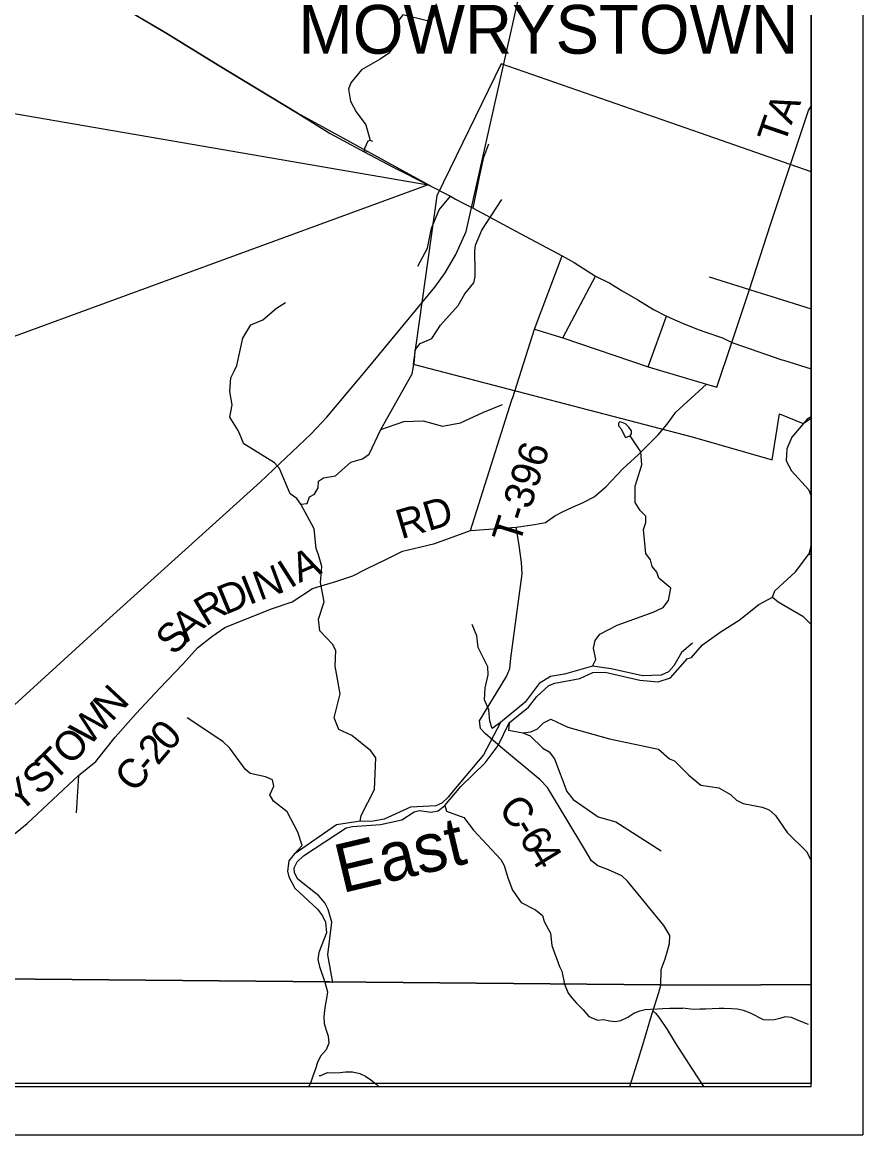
# Model space of a CAD drawing. Extents: x 0 to 34, y 0 to 22.
# Drawn here: x 7.367 to 9, y 14 to 16.162 of the extents above; entities that cross this region are included whole.
import ezdxf

# ---------------------------------------------------------------- set-up
doc = ezdxf.new("R2010")
doc.units = 0
for name, color, linetype in [('Default', 7, 'Continuous'), ('GM_X_City_Street', 7, 'Continuous'), ('GM_X_Corporation_Text', 7, 'Continuous'), ('GM_X_County_Road', 7, 'Continuous'), ('GM_X_County_Road_Text', 7, 'Continuous'), ('GM_X_Major_River', 7, 'Continuous'), ('GM_X_Major_River_Text', 7, 'Continuous'), ('GM_X_Minor_Lake', 7, 'Continuous'), ('GM_X_Minor_River', 7, 'Continuous'), ('GM_X_Rail_Line', 7, 'Continuous'), ('GM_X_State_Route', 7, 'Continuous'), ('GM_X_Township_Road', 7, 'Continuous'), ('GM_X_Township_Road_Text', 7, 'Continuous'), ('SH_Cut_Line', 7, 'Continuous'), ('SH_Data', 7, 'Continuous')]:
    doc.layers.add(name, color=color, linetype=linetype)

msp = doc.modelspace()

# ---------------------------------------------------------------- linework, layer by layer
at = {"layer": 'Default'}
msp.add_lwpolyline([(8.161, 15.8436), (7.9019, 15.9854), (7.7478, 16.0791), (7.6481, 16.1403), (7.4293, 16.2693), (7.2434, 16.3742), (6.998, 16.5438), (6.6485, 16.765), (6.4043, 16.9203), (6.0579, 17.1312), (5.7891, 17.2948), (5.4666, 17.4969), (4.8712, 17.8663), (4.7185, 17.9622), (4.6135, 18.0087), (4.4868, 18.0434), (4.3784, 18.0545), (4.2056, 18.0659), (3.9354, 18.0836), (3.6991, 18.1432)], dxfattribs=at)
for points in [[(8.9, 15.3927), (8.9, 15.8717), (8.685, 15.9464), (8.2976, 16.0814), (8.1729, 15.8246), (8.1267, 15.4975), (8.6688, 15.3564), (8.8242, 15.3119), (8.8384, 15.4014), (8.8841, 15.3823)], [(7.2008, 16.011), (8.1557, 15.8464), (7.2008, 15.4965)], [(7.3096, 14.0941), (8.9, 14.0941), (8.9, 14.2922), (8.7041, 14.2905), (8.6074, 14.2911), (7.3204, 14.3032)]]:
    msp.add_lwpolyline(points, close=True, dxfattribs=at)
at = {"layer": 'GM_X_City_Street'}
for p, q in [((8.4172, 15.5492), (8.4806, 15.6688)), ((8.8046, 15.6353), (8.8217, 15.6299)), ((8.8217, 15.6299), (8.9, 15.6054)), ((8.5832, 15.4923), (8.6188, 15.5911))]:
    msp.add_line(p, q, dxfattribs=at)
for points in [[(8.2431, 15.8007), (8.2553, 15.8615), (8.2638, 15.9002), (8.2737, 15.9259)], [(8.1359, 15.6885), (8.1546, 15.723), (8.162, 15.762), (8.1773, 15.7976), (8.199, 15.8241)], [(8.7014, 15.6676), (8.7797, 15.6431), (8.8046, 15.6353)], [(8.3624, 15.566), (8.4172, 15.5492), (8.5832, 15.4923), (8.6963, 15.4587)]]:
    msp.add_lwpolyline(points, dxfattribs=at)
at = {"layer": 'GM_X_County_Road'}
for points in [[(8.8581, 15.8821), (8.8587, 15.884), (8.8945, 15.9907), (8.9, 15.9994)], [(8.7459, 15.54), (8.7797, 15.6431), (8.8211, 15.7693), (8.8581, 15.8821)], [(8.6202, 15.381), (8.637, 15.4042), (8.6963, 15.4587), (8.7166, 15.4527), (8.7459, 15.54)], [(7.1628, 14.4308), (7.3766, 14.605), (7.4762, 14.6982), (7.51, 14.7255), (7.5477, 14.7727), (7.5884, 14.819), (7.6336, 14.8672), (7.6793, 14.9145), (7.7079, 14.9463), (7.7353, 14.9682), (7.761, 14.9856), (7.8172, 15.0084), (7.8512, 15.0222), (7.8917, 15.0356), (7.9309, 15.0614), (7.9542, 15.069), (7.9763, 15.075), (8.0092, 15.0866), (8.036, 15.1001), (8.0746, 15.1184), (8.1057, 15.1345), (8.1392, 15.1419), (8.1689, 15.1493), (8.2378, 15.1743), (8.3267, 15.181), (8.3621, 15.186), (8.3838, 15.1902), (8.4018, 15.2028), (8.4168, 15.2105), (8.4363, 15.22), (8.4566, 15.2287), (8.4781, 15.2401), (8.5012, 15.2594), (8.5337, 15.2941), (8.5642, 15.3224), (8.6028, 15.3601), (8.6202, 15.381)], [(8.6076, 14.2905), (8.6085, 14.3213), (8.6161, 14.3421), (8.6209, 14.3572), (8.6249, 14.3715), (8.6252, 14.3875), (8.6138, 14.407), (8.5432, 14.493), (8.532, 14.5034), (8.5063, 14.5149), (8.4852, 14.5229), (8.4729, 14.5322), (8.46, 14.5545), (8.3873, 14.6746), (8.3735, 14.6897), (8.2964, 14.7541), (8.2665, 14.7801), (8.2572, 14.7897), (8.2555, 14.8042), (8.3079, 14.8905), (8.3146, 14.906), (8.3161, 14.9261), (8.3384, 15.0904), (8.3372, 15.1121), (8.3325, 15.1452), (8.3267, 15.181)], [(8.5923, 14.2393), (8.5988, 14.2602), (8.6036, 14.2763), (8.6076, 14.2905)], [(8.5476, 14.0941), (8.5651, 14.1498), (8.5767, 14.1878), (8.5879, 14.2252), (8.5923, 14.2393)]]:
    msp.add_lwpolyline(points, dxfattribs=at)
at = {"layer": 'GM_X_Major_River'}
for p, q in [((8.8994, 15.1427), (8.8954, 15.1287)), ((8.8994, 15.1427), (8.9, 15.1447)), ((8.8954, 15.1287), (8.9, 15.1286)), ((7.9704, 14.2961), (7.9552, 14.2963))]:
    msp.add_line(p, q, dxfattribs=at)
for points in [[(8.9, 15.3952), (8.8919, 15.3905), (8.8625, 15.3561), (8.8526, 15.3331), (8.8511, 15.31), (8.8617, 15.2901), (8.8945, 15.2543), (8.9, 15.2421)], [(8.6671, 14.9273), (8.6884, 14.9523), (8.7252, 14.9783), (8.7597, 15.0001), (8.7982, 15.0305), (8.825, 15.0449), (8.8293, 15.057), (8.8694, 15.0939), (8.8954, 15.1287)], [(8.6691, 14.9553), (8.648, 14.9376), (8.6329, 14.9112), (8.6228, 14.9), (8.6087, 14.893), (8.5723, 14.892), (8.5113, 14.9057), (8.475, 14.9108), (8.4205, 14.8952), (8.3935, 14.8907), (8.3713, 14.877), (8.3442, 14.8405), (8.2962, 14.801), (8.2631, 14.7381), (8.2048, 14.6691), (8.1947, 14.6563), (8.1824, 14.6444), (8.1706, 14.6392), (8.1212, 14.6369), (8.0704, 14.6133), (8.0457, 14.6091), (8.0237, 14.6094), (7.9777, 14.6021), (7.8953, 14.5452), (7.8852, 14.5324), (7.8827, 14.512), (7.8852, 14.5013), (7.897, 14.4791), (7.9408, 14.4383), (7.9505, 14.4256), (7.956, 14.4134), (7.958, 14.3925), (7.9431, 14.354), (7.9414, 14.3408), (7.9446, 14.3267), (7.9552, 14.2963)], [(7.9704, 14.2961), (7.9608, 14.3496), (7.9686, 14.4129), (7.9613, 14.438), (7.955, 14.4506), (7.9435, 14.4644), (7.9026, 14.4965), (7.8959, 14.5091), (7.8957, 14.519), (7.9011, 14.5303), (7.9138, 14.5419), (7.9966, 14.5965), (8.0087, 14.5994), (8.0631, 14.6032), (8.1046, 14.6121), (8.1287, 14.6277), (8.1386, 14.6302), (8.1613, 14.6272), (8.175, 14.6297), (8.1884, 14.6401), (8.2193, 14.6768), (8.2666, 14.7229), (8.2918, 14.7567), (8.3133, 14.8007), (8.3271, 14.8123), (8.3509, 14.8309), (8.3671, 14.8516), (8.3902, 14.8733), (8.402, 14.878), (8.4504, 14.8865), (8.4756, 14.8983), (8.4995, 14.8994), (8.5672, 14.8833), (8.6028, 14.8805), (8.6265, 14.8878), (8.6596, 14.9256), (8.6671, 14.9273)], [(7.9552, 14.2963), (7.9604, 14.278), (7.9583, 14.2647), (7.9559, 14.2511), (7.9542, 14.2412), (7.9529, 14.2291), (7.9534, 14.2162), (7.9578, 14.2032), (7.9618, 14.1914), (7.9627, 14.1781), (7.9576, 14.1653), (7.9468, 14.1525), (7.9405, 14.1405), (7.9369, 14.1284), (7.9322, 14.1156), (7.9278, 14.102), (7.924, 14.0941)]]:
    msp.add_lwpolyline(points, dxfattribs=at)
at = {"layer": 'GM_X_Minor_Lake'}
for points in [[(8.0318, 15.9169), (8.031, 15.9108), (8.0355, 15.91)], [(8.0388, 15.9312), (8.0318, 15.9169)], [(8.0483, 15.9307), (8.043, 15.9323), (8.0388, 15.9312)], [(8.5481, 15.3583), (8.5508, 15.3624), (8.5505, 15.3681), (8.5453, 15.3754), (8.5389, 15.3815), (8.5329, 15.3843), (8.5283, 15.3855), (8.5256, 15.3833), (8.5256, 15.3776), (8.5304, 15.3718), (8.5337, 15.3649), (8.5389, 15.3554)], [(8.5389, 15.3554), (8.5481, 15.3583)]]:
    msp.add_lwpolyline(points, dxfattribs=at)
at = {"layer": 'GM_X_Minor_River'}
for points in [[(8.1712, 16.1979), (8.1659, 16.1722), (8.1537, 16.1648), (8.1064, 16.1769), (8.0983, 16.1656), (8.0881, 16.1138), (8.0788, 16.1017), (8.0627, 16.0906), (8.0264, 16.0695), (8.0055, 16.0444), (8.0012, 16.0319), (8.005, 16.0087), (8.0161, 15.988), (8.0347, 15.9627), (8.043, 15.9323)], [(7.9086, 15.2257), (7.9204, 15.2271), (7.9255, 15.2399), (7.9351, 15.2451), (7.9421, 15.2571), (7.943, 15.27), (7.9526, 15.2771), (7.9758, 15.2806), (8.0054, 15.3075), (8.0279, 15.314), (8.0409, 15.3225), (8.0636, 15.3704), (8.1247, 15.4788), (8.1289, 15.5042), (8.1303, 15.5254), (8.1399, 15.5378), (8.1629, 15.5477), (8.1799, 15.5733), (8.2138, 15.6115), (8.2271, 15.6345), (8.2444, 15.6555), (8.2469, 15.6676), (8.2471, 15.6786), (8.2461, 15.7173), (8.2474, 15.7287), (8.2599, 15.7581), (8.2991, 15.8175)], [(8.0237, 14.6094), (8.0254, 14.6208), (8.0515, 14.6709), (8.0539, 14.7323), (8.0442, 14.7465), (8.0074, 14.7758), (7.9825, 14.7879), (7.973, 14.8101), (7.985, 14.857), (7.9748, 14.911), (7.9764, 14.9413), (7.9697, 14.9532), (7.9454, 14.9797), (7.9427, 15.0018), (7.9538, 15.0361), (7.9463, 15.0734), (7.949, 15.1045), (7.9429, 15.127), (7.9381, 15.1392), (7.9345, 15.1776), (7.9086, 15.2257), (7.9004, 15.2369), (7.8876, 15.2458), (7.8667, 15.2946), (7.8574, 15.3058), (7.7976, 15.3427), (7.7865, 15.369), (7.7706, 15.3947), (7.7751, 15.4185), (7.7705, 15.4444), (7.7724, 15.4709), (7.7787, 15.4841), (7.7838, 15.495), (7.7959, 15.5484), (7.8114, 15.5743), (7.8343, 15.5839), (7.8612, 15.6066), (7.8784, 15.6178)], [(8.0636, 15.3704), (8.1082, 15.3861), (8.1458, 15.3878), (8.1836, 15.3774), (8.2186, 15.3838), (8.2622, 15.404), (8.3003, 15.4194)], [(8.475, 14.9108), (8.4812, 14.924), (8.477, 14.946), (8.4799, 14.9604), (8.4895, 14.9728), (8.5232, 14.9906), (8.5926, 15.0158), (8.6121, 15.0246), (8.6229, 15.0385), (8.627, 15.0623), (8.6041, 15.082), (8.6001, 15.0934), (8.5908, 15.1042), (8.5876, 15.1171), (8.5786, 15.1298), (8.574, 15.1765), (8.5783, 15.1901), (8.5789, 15.2026), (8.5677, 15.2134), (8.5576, 15.2287), (8.5581, 15.2606), (8.5708, 15.3022), (8.5689, 15.3272), (8.5481, 15.3583)], [(8.825, 15.0449), (8.8354, 15.036), (8.8839, 15.0079), (8.9, 14.9914)], [(8.2962, 14.801), (8.2801, 14.7894), (8.2754, 14.8036), (8.2734, 14.8256), (8.2653, 14.8451), (8.2668, 14.8689), (8.2725, 14.8939), (8.2719, 14.9095), (8.2527, 14.9469), (8.25, 14.9694), (8.2412, 14.9919)], [(7.8953, 14.5452), (7.9107, 14.562), (7.9027, 14.5883), (7.882, 14.6273), (7.8553, 14.6482), (7.8479, 14.6608), (7.8561, 14.6774), (7.8533, 14.6896), (7.8397, 14.6959), (7.8098, 14.7023), (7.8001, 14.7108), (7.7703, 14.7511), (7.7568, 14.7646), (7.6876, 14.8103)], [(8.3133, 14.8007), (8.3119, 14.7863), (8.3396, 14.7814), (8.3539, 14.7751), (8.3782, 14.7513), (8.3907, 14.7443), (8.4011, 14.7304), (8.4253, 14.6671), (8.4372, 14.6518), (8.4857, 14.6181), (8.5201, 14.6085), (8.6081, 14.5515)], [(8.3396, 14.7814), (8.3555, 14.7831), (8.3681, 14.789), (8.3801, 14.8009), (8.3938, 14.808), (8.427, 14.7919), (8.5083, 14.7692), (8.6029, 14.7496), (8.6246, 14.7307), (8.6345, 14.7268), (8.6621, 14.6986)], [(8.6621, 14.6986), (8.6853, 14.6796), (8.7204, 14.6741), (8.7434, 14.6616), (8.7545, 14.65), (8.7677, 14.6437), (8.8048, 14.637), (8.8179, 14.6315), (8.8303, 14.6207), (8.8532, 14.5877), (8.8905, 14.5506), (8.8986, 14.5353), (8.9, 14.5342)], [(8.1884, 14.6401), (8.1913, 14.6287), (8.2253, 14.6168), (8.2439, 14.5923), (8.2966, 14.535), (8.3033, 14.5235), (8.3106, 14.4995), (8.3193, 14.4755), (8.3365, 14.4517), (8.3644, 14.4373), (8.3779, 14.4264), (8.3811, 14.4146), (8.3937, 14.3917), (8.396, 14.3678), (8.411, 14.3273), (8.4154, 14.3178), (8.4209, 14.2927)], [(8.4209, 14.2927), (8.4279, 14.2755), (8.435, 14.2659), (8.4439, 14.2555), (8.4566, 14.2429), (8.4682, 14.2298), (8.4844, 14.2228), (8.4973, 14.2237), (8.5078, 14.2213), (8.5199, 14.22), (8.5298, 14.2222), (8.5435, 14.2288), (8.5553, 14.2363), (8.5671, 14.241), (8.577, 14.2432), (8.588, 14.2438), (8.6016, 14.2448), (8.6114, 14.2454), (8.6251, 14.246), (8.636, 14.2462), (8.65, 14.246)], [(8.8947, 14.2144), (8.883, 14.2191), (8.8721, 14.2235), (8.8616, 14.2278), (8.8495, 14.2295), (8.8388, 14.2262), (8.8286, 14.2233), (8.8176, 14.223), (8.807, 14.2236), (8.7822, 14.2364), (8.7682, 14.2412), (8.7561, 14.244), (8.7448, 14.2445), (8.7308, 14.2454), (8.7209, 14.2452), (8.7073, 14.2446), (8.6948, 14.2444), (8.6838, 14.2442), (8.6709, 14.2436), (8.65, 14.246)], [(7.9443, 14.115), (7.9471, 14.1152), (7.9604, 14.1207), (7.9737, 14.1202), (7.9847, 14.1208), (7.9953, 14.1222), (8.0089, 14.122), (8.0229, 14.1192), (8.0338, 14.1141), (8.0443, 14.1067), (8.0566, 14.0971), (8.06, 14.0941)]]:
    msp.add_lwpolyline(points, dxfattribs=at)
at = {"layer": 'GM_X_Rail_Line'}
msp.add_lwpolyline([(6.7762, 14.3109), (6.9297, 14.4507), (7.5373, 15.0047), (7.83, 15.2691), (7.9287, 15.3625), (7.9592, 15.3949), (8.0363, 15.4875), (8.1684, 15.6475), (8.1886, 15.6755), (8.2095, 15.7107), (8.2296, 15.7554), (8.4079, 16.5494), (8.4762, 16.897), (8.4969, 16.9945), (8.5214, 17.0999), (8.5608, 17.4879), (8.571, 17.5663), (8.6067, 17.7431), (8.6649, 18.0046), (8.6886, 18.0902), (8.7141, 18.1631), (8.8658, 18.463), (8.9, 18.5325)], dxfattribs=at)
at = {"layer": 'GM_X_State_Route'}
msp.add_line((8.161, 15.8436), (8.1963, 15.8255), dxfattribs=at)
for points in [[(7.4992, 16.2294), (7.6481, 16.1403), (7.7478, 16.0791), (7.9019, 15.9854), (7.9655, 15.946), (8.0314, 15.9107), (8.0878, 15.8809), (8.1557, 15.8464), (8.161, 15.8436)], [(8.1963, 15.8255), (8.199, 15.8241), (8.2089, 15.8186), (8.2252, 15.8098), (8.2315, 15.8066)], [(8.2315, 15.8066), (8.2431, 15.8007), (8.3344, 15.7518), (8.4158, 15.7085)], [(8.4158, 15.7085), (8.4393, 15.6954), (8.4487, 15.6895), (8.4806, 15.6688), (8.5084, 15.6549), (8.5326, 15.6402), (8.5632, 15.6227), (8.5934, 15.6041), (8.6188, 15.5911), (8.6498, 15.5771), (8.6802, 15.5654)], [(8.6802, 15.5654), (8.6931, 15.5604), (8.7275, 15.5487)], [(8.7275, 15.5487), (8.7304, 15.5477), (8.7459, 15.54)], [(8.7459, 15.54), (8.7498, 15.5388), (8.7682, 15.5323), (8.8389, 15.5074), (8.8428, 15.5062)], [(8.8428, 15.5062), (8.8458, 15.5053), (8.9, 15.4884)]]:
    msp.add_lwpolyline(points, dxfattribs=at)
at = {"layer": 'GM_X_Township_Road'}
msp.add_line((7.4762, 14.6982), (7.4719, 14.6257), dxfattribs=at)
for points in [[(8.3201, 15.4332), (8.3624, 15.566), (8.4158, 15.7085)], [(8.2378, 15.1743), (8.3186, 15.4283), (8.3201, 15.4332)], [(8.6912, 14.0941), (8.6694, 14.1276), (8.6364, 14.1788), (8.6206, 14.2046), (8.6055, 14.2268), (8.6014, 14.2322), (8.5985, 14.2355), (8.5974, 14.2366), (8.5962, 14.2376), (8.5954, 14.2382), (8.5943, 14.2387), (8.5923, 14.2393)]]:
    msp.add_lwpolyline(points, dxfattribs=at)
at = {"layer": 'SH_Cut_Line'}
msp.add_lwpolyline([(2.3212, 18.6531), (2.2797, 17.8302), (2.2668, 17.0936), (2.2632, 16.8811), (2.258, 16.7775), (2.1837, 15.746), (2.1, 14.637), (2.1, 14.4457), (2.4012, 14.4298), (2.4436, 14.4284), (2.5802, 14.4232), (3.783, 14.3901), (4.0144, 14.3862), (4.819, 14.3535), (4.9366, 14.3421), (5.0616, 14.3309), (5.4793, 14.3187), (6.7418, 14.3069), (6.8864, 14.3056), (7.3204, 14.3032), (8.6074, 14.2911), (8.7041, 14.2905), (8.9, 14.2922), (8.9, 20.8941)], dxfattribs=at)
at = {"layer": 'SH_Data'}
for p, q in [((9, 21), (9, 14)), ((8.9, 20.9), (8.9, 14.1)), ((2.1, 14.1), (8.9, 14.1)), ((2, 14), (9, 14))]:
    msp.add_line(p, q, dxfattribs=at)

# ---------------------------------------------------------------- texts
at = {"layer": 'GM_X_Corporation_Text'}
msp.add_text('MOWRYSTOWN', height=0.0947, rotation=0, dxfattribs=at).set_placement((7.9038, 16.1012))
at = {"layer": 'GM_X_County_Road_Text'}
for s, height, rotation, p in [('A', 0.0568, 66.8743, (8.8612, 15.9614)), ('T', 0.0568, 71.0162, (8.8478, 15.9223)), ('RD', 0.05682, 16.5575, (8.1034, 15.1573)), ('A', 0.0568, 23.3859, (7.9052, 15.072)), ('I', 0.0568, 32.4386, (7.8876, 15.0606)), ('N', 0.0568, 20.1919, (7.8288, 15.0375)), ('D', 0.0568, 22.2912, (7.7614, 15.0101)), ('I', 0.0568, 21.8275, (7.8075, 15.029)), ('R', 0.0568, 30.9925, (7.7234, 14.9871)), ('A', 0.0568, 40.3081, (7.6873, 14.9561)), ('S', 0.0568, 46.0937, (7.6618, 14.9296)), ('N', 0.0568, 47.159, (7.541, 14.8009)), ('W', 0.0568, 47.1585, (7.4962, 14.7526)), ('0', 0.0568, 48.2251, (7.6528, 14.7424)), ('O', 0.0568, 46.239, (7.4609, 14.7158)), ('2', 0.0568, 49.6121, (7.6304, 14.716)), ('T', 0.0568, 44.1101, (7.4288, 14.6846)), ('S', 0.0568, 43.0458, (7.4, 14.6576)), ('C', 0.0568, 49.985, (7.5854, 14.6625)), ('-', 0.0568, 49.9046, (7.6154, 14.6982)), ('Y', 0.0568, 42.1619, (7.3622, 14.6234)), ('C', 0.0568, 309.6632, (8.2899, 14.6315)), ('-', 0.0568, 301.6546, (8.3185, 14.5973)), ('6', 0.0568, 301.4466, (8.3307, 14.5774)), ('4', 0.0568, 301.4047, (8.3489, 14.5476))]:
    msp.add_text(s, height=height, rotation=rotation, dxfattribs=at).set_placement(p)
at = {"layer": 'GM_X_Major_River_Text'}
msp.add_text('East', height=0.0947, rotation=13.3677, dxfattribs=at).set_placement((7.9881, 14.4692))
at = {"layer": 'GM_X_Township_Road_Text'}
msp.add_text('T-396', height=0.05682, rotation=72.5454, dxfattribs=at).set_placement((8.333, 15.1455))

doc.saveas('drawing.dxf')
